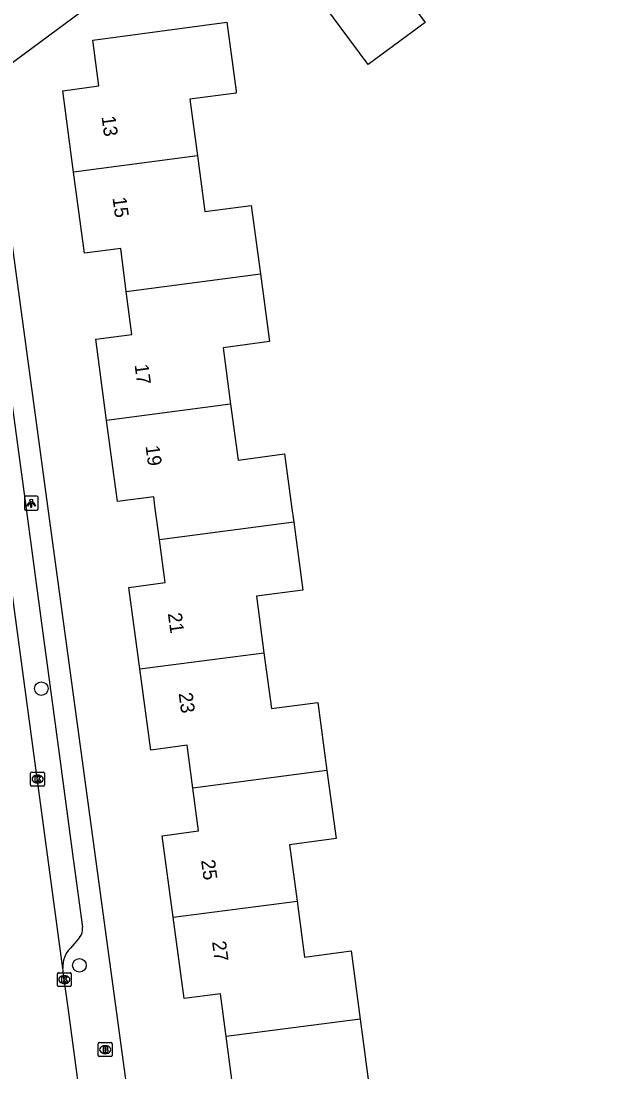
# Model space of a CAD drawing. Extents: x 163427 to 164190, y 380331 to 381641.
# Drawn here: x 163657.9 to 163700.4, y 381209.4 to 381284.8 of the extents above; entities that cross this region are included whole.
import ezdxf

# ---------------------------------------------------------------- set-up
doc = ezdxf.new("R2010")
doc.units = 0
for name, color, linetype in [('IMGEO_Boom', 7, 'Continuous'), ('IMGEO_Brandkraan', 7, 'Continuous'), ('IMGEO_Kolk', 7, 'Continuous'), ('IMGEO_Lichtpunt', 7, 'Continuous'), ('IMGEO_Pand', 7, 'Continuous'), ('IMGEO_Pand_nummerreeks', 7, 'Continuous'), ('IMGEO_Rijbaan_lokaal_open', 7, 'Continuous'), ('IMGEO_Voetpad_open', 7, 'Continuous')]:
    doc.layers.add(name, color=color, linetype=linetype)

msp = doc.modelspace()

# ---------------------------------------------------------------- linework, layer by layer
at = {"layer": 'IMGEO_Boom'}
for centre in [(163659.351, 381236.902), (163662.093, 381217.036)]:
    msp.add_circle(centre, 0.489, dxfattribs=at)
at = {"layer": 'IMGEO_Brandkraan'}
for p, q in [((163663.445, 381210.559), (163663.445, 381211.411)), ((163663.52, 381211.485), (163664.372, 381211.485)), ((163663.933, 381211.265), (163663.958, 381211.265)), ((163664.446, 381211.411), (163664.446, 381210.559)), ((163663.956, 381210.705), (163663.931, 381210.705)), ((163664.372, 381210.485), (163663.52, 381210.485))]:
    msp.add_line(p, q, dxfattribs=at)
for points in [[(163663.445, 381210.559), (163663.445, 381211.411)], [(163663.52, 381211.485), (163664.372, 381211.485)], [(163664.446, 381211.411), (163664.446, 381210.559)], [(163663.793, 381211.185), (163663.793, 381210.785), (163664.006, 381210.785)], [(163664.024, 381211.185), (163663.793, 381211.185)], [(163663.972, 381211.104), (163663.918, 381211.104), (163663.918, 381211.028)], [(163663.918, 381211.028), (163663.971, 381211.028)], [(163663.98, 381210.952), (163663.918, 381210.952), (163663.918, 381210.871)], [(163663.918, 381210.871), (163663.98, 381210.871)], [(163664.372, 381210.485), (163663.52, 381210.485)]]:
    msp.add_lwpolyline(points, dxfattribs=at)
for centre, radius, start, end in [((163663.522, 381211.409), 0.0765, 91.55205, 178.44795), ((163663.522, 381211.409), 0.0765, 91.55205, 178.44795), ((163664.37, 381211.409), 0.0765, 1.55205, 88.44795), ((163664.37, 381211.409), 0.0765, 1.55205, 88.44795), ((163663.522, 381210.561), 0.0765, 181.55205, 268.44795), ((163663.522, 381210.561), 0.0765, 181.55205, 268.44795), ((163663.973, 381211.066), 0.0379, 267.82845, 90.93552), ((163663.981, 381210.911), 0.0404, 269.87594, 90.50774), ((163664.012, 381211.036), 0.251, 268.66757, 293.53466), ((163664.028, 381211.04), 0.145, 59.4692, 91.53667), ((163664.053, 381211.087), 0.0922, 285.51372, 58.15012), ((163664.058, 381210.895), 0.105, 301.31148, 78.98903), ((163664.37, 381210.561), 0.0765, 271.55205, 358.44795), ((163664.37, 381210.561), 0.0765, 271.55205, 358.44795)]:
    msp.add_arc(centre, radius, start, end, dxfattribs=at)
for centre, major_axis, ratio, start_param, end_param in [((163663.932, 381210.985), (-0.387, 0.002), 0.722429, 4.712389, 7.853982), ((163663.957, 381210.985), (-0.39, 0.002), 0.717154, 1.570796, 4.712389)]:
    msp.add_ellipse(centre, major_axis=major_axis, ratio=ratio, start_param=start_param, end_param=end_param, dxfattribs=at)
at = {"layer": 'IMGEO_Kolk'}
for p, q in [((163658.659, 381230.912), (163659.511, 381230.912)), ((163658.584, 381229.986), (163658.584, 381230.838)), ((163659.095, 381230.132), (163659.07, 381230.132)), ((163659.072, 381230.692), (163659.097, 381230.692)), ((163659.585, 381230.838), (163659.585, 381229.986)), ((163659.511, 381229.912), (163658.659, 381229.912)), ((163660.505, 381215.584), (163660.505, 381216.436)), ((163660.58, 381216.51), (163661.432, 381216.51)), ((163660.993, 381216.29), (163661.018, 381216.29)), ((163661.506, 381216.436), (163661.506, 381215.584)), ((163661.432, 381215.51), (163660.58, 381215.51)), ((163661.016, 381215.73), (163660.991, 381215.73))]:
    msp.add_line(p, q, dxfattribs=at)
for points in [[(163658.659, 381230.912), (163659.511, 381230.912)], [(163658.584, 381229.986), (163658.584, 381230.838)], [(163658.905, 381230.612), (163659.028, 381230.612), (163659.028, 381230.461), (163659.158, 381230.612), (163659.322, 381230.612), (163659.176, 381230.461), (163659.329, 381230.212), (163659.177, 381230.212), (163659.092, 381230.376), (163659.028, 381230.309), (163659.028, 381230.212), (163658.905, 381230.212), (163658.905, 381230.612)], [(163659.585, 381230.838), (163659.585, 381229.986)], [(163659.511, 381229.912), (163658.659, 381229.912)], [(163660.505, 381215.584), (163660.505, 381216.436)], [(163660.58, 381216.51), (163661.432, 381216.51)], [(163660.826, 381216.21), (163660.949, 381216.21), (163660.949, 381216.059), (163661.079, 381216.21), (163661.243, 381216.21), (163661.097, 381216.059), (163661.25, 381215.81), (163661.098, 381215.81), (163661.013, 381215.974), (163660.949, 381215.907), (163660.949, 381215.81), (163660.826, 381215.81), (163660.826, 381216.21)], [(163661.506, 381216.436), (163661.506, 381215.584)], [(163661.432, 381215.51), (163660.58, 381215.51)]]:
    msp.add_lwpolyline(points, dxfattribs=at)
for centre, start, end in [((163658.661, 381230.836), 91.55205, 178.44795), ((163658.661, 381230.836), 91.55205, 178.44795), ((163659.509, 381230.836), 1.55205, 88.44795), ((163659.509, 381230.836), 1.55205, 88.44795), ((163658.661, 381229.988), 181.55205, 268.44795), ((163658.661, 381229.988), 181.55205, 268.44795), ((163659.509, 381229.988), 271.55205, 358.44795), ((163659.509, 381229.988), 271.55205, 358.44795), ((163660.582, 381216.434), 91.55205, 178.44795), ((163660.582, 381216.434), 91.55205, 178.44795), ((163661.43, 381216.434), 1.55205, 88.44795), ((163661.43, 381216.434), 1.55205, 88.44795), ((163660.582, 381215.586), 181.55205, 268.44795), ((163660.582, 381215.586), 181.55205, 268.44795), ((163661.43, 381215.586), 271.55205, 358.44795), ((163661.43, 381215.586), 271.55205, 358.44795)]:
    msp.add_arc(centre, 0.0765, start, end, dxfattribs=at)
for centre, major_axis, ratio, start_param, end_param in [((163659.071, 381230.412), (-0.387, 0.002), 0.722429, 4.712389, 7.853982), ((163659.096, 381230.412), (-0.39, 0.002), 0.717154, 1.570796, 4.712389), ((163660.992, 381216.01), (-0.387, 0.002), 0.722429, 4.712389, 7.853982), ((163661.017, 381216.01), (-0.39, 0.002), 0.717154, 1.570796, 4.712389)]:
    msp.add_ellipse(centre, major_axis=major_axis, ratio=ratio, start_param=start_param, end_param=end_param, dxfattribs=at)
at = {"layer": 'IMGEO_Lichtpunt'}
for p, q in [((163658.133, 381250.619), (163658.133, 381249.812)), ((163658.133, 381250.619), (163658.133, 381249.812)), ((163659.035, 381250.714), (163658.227, 381250.714)), ((163659.035, 381250.714), (163658.227, 381250.714)), ((163659.129, 381249.812), (163659.129, 381250.619)), ((163659.129, 381249.812), (163659.129, 381250.619)), ((163658.227, 381249.718), (163659.035, 381249.718)), ((163658.227, 381249.718), (163659.035, 381249.718))]:
    msp.add_line(p, q, dxfattribs=at)
for points in [[(163658.507, 381250.283), (163658.546, 381250.255), (163658.358, 381249.993), (163658.32, 381250.02), (163658.507, 381250.283)], [(163658.609, 381250.235), (163658.656, 381250.235), (163658.656, 381249.913), (163658.609, 381249.913), (163658.609, 381250.235)], [(163658.719, 381250.255), (163658.757, 381250.282), (163658.944, 381250.02), (163658.905, 381249.992), (163658.719, 381250.255)]]:
    msp.add_lwpolyline(points, dxfattribs=at)
msp.add_circle((163658.632, 381250.417), 0.0994, dxfattribs=at)
for centre, start, end in [((163658.227, 381250.619), 90, 180), ((163658.227, 381250.619), 90, 180), ((163659.035, 381250.619), 0, 90), ((163659.035, 381250.619), 0, 90), ((163658.227, 381249.812), 180, 270), ((163658.227, 381249.812), 180, 270), ((163659.035, 381249.812), 270, 0), ((163659.035, 381249.812), 270, 360)]:
    msp.add_arc(centre, 0.0946, start, end, dxfattribs=at)
at = {"layer": 'IMGEO_Pand'}
for points in [[(163688.221, 381289.839), (163684.943, 381287.417), (163686.931, 381284.727), (163682.836, 381281.703), (163681.524, 381283.478), (163678.553, 381287.5)], [(163661.675, 381273.985), (163660.887, 381279.815), (163663.495, 381280.18), (163663.059, 381283.468), (163672.685, 381284.747), (163673.348, 381279.792), (163673.365, 381279.667), (163670.028, 381279.221), (163670.571, 381275.166)], [(163670.571, 381275.166), (163661.675, 381273.985)], [(163670.571, 381275.166), (163671.109, 381271.151), (163674.447, 381271.599), (163675.105, 381266.685)], [(163665.46, 381265.418), (163665.061, 381268.494), (163662.463, 381268.157), (163661.675, 381273.985)], [(163665.46, 381265.418), (163675.105, 381266.685)], [(163675.105, 381266.685), (163675.755, 381261.824), (163672.418, 381261.379), (163672.961, 381257.323)], [(163664.048, 381256.165), (163663.261, 381262.001), (163665.86, 381262.339), (163665.46, 381265.418)], [(163672.961, 381257.323), (163664.048, 381256.165)], [(163672.961, 381257.323), (163673.499, 381253.309), (163676.837, 381253.755), (163677.34, 381250), (163677.493, 381248.853)], [(163667.839, 381247.592), (163667.521, 381250), (163667.432, 381250.671), (163664.835, 381250.328), (163664.048, 381256.165)], [(163677.493, 381248.853), (163667.839, 381247.592)], [(163677.493, 381248.853), (163678.145, 381243.981), (163674.808, 381243.535), (163675.351, 381239.482)], [(163666.436, 381238.33), (163665.646, 381244.173), (163668.244, 381244.517), (163667.839, 381247.592)], [(163666.436, 381238.33), (163675.351, 381239.482)], [(163675.351, 381239.482), (163675.889, 381235.465), (163679.227, 381235.912), (163679.881, 381231.021)], [(163670.241, 381229.762), (163669.829, 381232.835), (163667.226, 381232.486), (163666.436, 381238.33)], [(163679.881, 381231.021), (163670.241, 381229.762)], [(163679.881, 381231.021), (163680.535, 381226.137), (163677.199, 381225.692), (163677.741, 381221.645)], [(163668.84, 381220.495), (163668.049, 381226.34), (163670.653, 381226.69), (163670.241, 381229.762)], [(163668.84, 381220.495), (163677.741, 381221.645)], [(163677.741, 381221.645), (163678.278, 381217.631), (163681.616, 381218.079), (163682.273, 381213.17)], [(163672.643, 381211.918), (163672.229, 381214.999), (163669.631, 381214.65), (163668.84, 381220.495)], [(163682.273, 381213.17), (163672.643, 381211.918)], [(163682.273, 381213.17), (163682.924, 381208.304), (163679.598, 381207.86), (163680.14, 381203.81)], [(163671.227, 381202.645), (163670.45, 381208.482), (163673.058, 381208.834), (163672.643, 381211.918)]]:
    msp.add_lwpolyline(points, dxfattribs=at)
at = {"layer": 'IMGEO_Rijbaan_lokaal_open'}
for points in [[(163660.901, 381216.818), (163656.419, 381250), (163652.592, 381278.335)], [(163662.857, 381202.129), (163662.302, 381206.299), (163661.3, 381213.825), (163661.002, 381216.038), (163660.901, 381216.818)]]:
    msp.add_lwpolyline(points, dxfattribs=at)
at = {"layer": 'IMGEO_Voetpad_open'}
for points in [[(163718.602, 381327.167), (163657.027, 381281.631)], [(163655.852, 381278.964), (163659.796, 381250), (163666.598, 381200.045)], [(163654.726, 381275.886), (163655.92, 381267.061), (163656.939, 381259.527), (163658.228, 381250), (163658.277, 381249.637), (163659.291, 381242.138), (163660.633, 381232.217), (163661.651, 381224.692), (163662.317, 381219.765)], [(163662.104, 381219.044), (163661.443, 381218.272)]]:
    msp.add_lwpolyline(points, dxfattribs=at)
for centre, radius, start, end in [((163661.41, 381219.641), 0.916, 319.30878, 7.77452), ((163662.711, 381216.971), 1.816, 134.27007, 184.84256)]:
    msp.add_arc(centre, radius, start, end, dxfattribs=at)

# ---------------------------------------------------------------- texts
at = {"layer": 'IMGEO_Pand_nummerreeks'}
for s, rotation, p in [('13', 277.69892, (163663.68, 381277.967)), ('15', 277.69892, (163664.468, 381272.138)), ('17', 277.67951, (163666.053, 381260.148)), ('19', 277.67951, (163666.84, 381254.312)), ('21', 277.69931, (163668.443, 381242.296)), ('23', 277.69931, (163669.218, 381236.564)), ('25', 277.70697, (163670.831, 381224.574)), ('27', 277.70697, (163671.622, 381218.729))]:
    msp.add_text(s, height=1, rotation=rotation, dxfattribs=at).set_placement(p)

doc.saveas('drawing.dxf')
